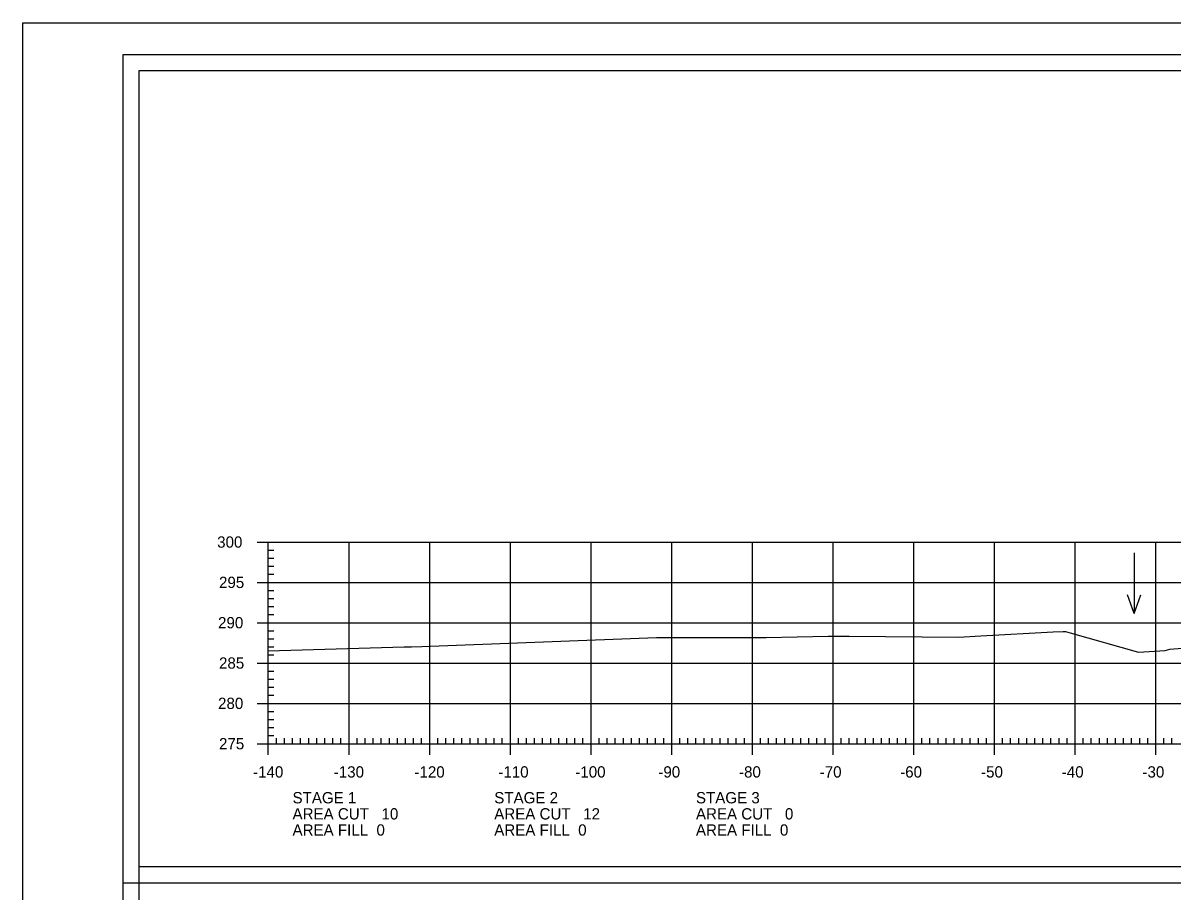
# Model space of a CAD drawing. Extents: x 1368713 to 1370673, y 380279 to 380950.
# Drawn here: x 1370339.2 to 1370481.6, y 380842.8 to 380950.4 of the extents above; entities that cross this region are included whole.
import ezdxf

# ---------------------------------------------------------------- set-up
doc = ezdxf.new("R2010")
doc.units = 0
for name, color, linetype in [('R_Axis', 7, 'Continuous'), ('R_Axis Annot', 7, 'Continuous'), ('R_Border', 7, 'Continuous'), ('R_Border Plan-Plan', 7, 'Continuous'), ('R_Exist Surface', 7, 'Continuous'), ('R_Grid', 7, 'Continuous'), ('R_No Plot', 7, 'Continuous'), ('R_Water Annot', 7, 'Continuous')]:
    doc.layers.add(name, color=color, linetype=linetype)

msp = doc.modelspace()

# ---------------------------------------------------------------- linework, layer by layer
at = {"layer": 'R_Axis'}
for p, q in [((1370368.23, 380886.09), (1370371.03, 380886.09)), ((1370369.63, 380861.09), (1370369.63, 380886.09)), ((1370369.63, 380885.09), (1370370.33, 380885.09)), ((1370369.63, 380884.09), (1370370.33, 380884.09)), ((1370369.63, 380883.09), (1370370.33, 380883.09)), ((1370369.63, 380882.09), (1370370.33, 380882.09)), ((1370368.23, 380881.09), (1370371.03, 380881.09)), ((1370369.63, 380880.09), (1370370.33, 380880.09)), ((1370369.63, 380879.09), (1370370.33, 380879.09)), ((1370369.63, 380878.09), (1370370.33, 380878.09)), ((1370369.63, 380877.09), (1370370.33, 380877.09)), ((1370368.23, 380876.09), (1370371.03, 380876.09)), ((1370369.63, 380875.09), (1370370.33, 380875.09)), ((1370369.63, 380874.09), (1370370.33, 380874.09)), ((1370369.63, 380873.09), (1370370.33, 380873.09)), ((1370368.23, 380871.09), (1370371.03, 380871.09)), ((1370369.63, 380872.09), (1370370.33, 380872.09)), ((1370369.63, 380870.09), (1370370.33, 380870.09)), ((1370369.63, 380869.09), (1370370.33, 380869.09)), ((1370369.63, 380868.09), (1370370.33, 380868.09)), ((1370369.63, 380867.09), (1370370.33, 380867.09)), ((1370368.23, 380866.09), (1370371.03, 380866.09)), ((1370369.63, 380865.09), (1370370.33, 380865.09)), ((1370369.63, 380864.09), (1370370.33, 380864.09)), ((1370369.63, 380863.09), (1370370.33, 380863.09)), ((1370369.63, 380859.69), (1370369.63, 380862.49)), ((1370379.63, 380859.69), (1370379.63, 380862.49)), ((1370389.63, 380859.69), (1370389.63, 380862.49)), ((1370399.63, 380859.69), (1370399.63, 380862.49)), ((1370409.63, 380859.69), (1370409.63, 380862.49)), ((1370419.63, 380859.69), (1370419.63, 380862.49)), ((1370429.63, 380859.69), (1370429.63, 380862.49)), ((1370439.63, 380859.69), (1370439.63, 380862.49)), ((1370449.63, 380859.69), (1370449.63, 380862.49)), ((1370459.63, 380859.69), (1370459.63, 380862.49)), ((1370469.63, 380859.69), (1370469.63, 380862.49)), ((1370479.63, 380859.69), (1370479.63, 380862.49)), ((1370368.23, 380861.09), (1370371.03, 380861.09)), ((1370369.63, 380862.09), (1370370.33, 380862.09)), ((1370369.63, 380861.09), (1370649.63, 380861.09)), ((1370370.63, 380861.09), (1370370.63, 380861.79)), ((1370371.63, 380861.09), (1370371.63, 380861.79)), ((1370372.63, 380861.09), (1370372.63, 380861.79)), ((1370373.63, 380861.09), (1370373.63, 380861.79)), ((1370374.63, 380861.09), (1370374.63, 380861.79)), ((1370375.63, 380861.09), (1370375.63, 380861.79)), ((1370376.63, 380861.09), (1370376.63, 380861.79)), ((1370377.63, 380861.09), (1370377.63, 380861.79)), ((1370378.63, 380861.09), (1370378.63, 380861.79)), ((1370380.63, 380861.09), (1370380.63, 380861.79)), ((1370381.63, 380861.09), (1370381.63, 380861.79)), ((1370382.63, 380861.09), (1370382.63, 380861.79)), ((1370383.63, 380861.09), (1370383.63, 380861.79)), ((1370384.63, 380861.09), (1370384.63, 380861.79)), ((1370385.63, 380861.09), (1370385.63, 380861.79)), ((1370386.63, 380861.09), (1370386.63, 380861.79)), ((1370387.63, 380861.09), (1370387.63, 380861.79)), ((1370388.63, 380861.09), (1370388.63, 380861.79)), ((1370390.63, 380861.09), (1370390.63, 380861.79)), ((1370391.63, 380861.09), (1370391.63, 380861.79)), ((1370392.63, 380861.09), (1370392.63, 380861.79)), ((1370393.63, 380861.09), (1370393.63, 380861.79)), ((1370394.63, 380861.09), (1370394.63, 380861.79)), ((1370395.63, 380861.09), (1370395.63, 380861.79)), ((1370396.63, 380861.09), (1370396.63, 380861.79)), ((1370397.63, 380861.09), (1370397.63, 380861.79)), ((1370398.63, 380861.09), (1370398.63, 380861.79)), ((1370400.63, 380861.09), (1370400.63, 380861.79)), ((1370401.63, 380861.09), (1370401.63, 380861.79)), ((1370402.63, 380861.09), (1370402.63, 380861.79)), ((1370403.63, 380861.09), (1370403.63, 380861.79)), ((1370404.63, 380861.09), (1370404.63, 380861.79)), ((1370405.63, 380861.09), (1370405.63, 380861.79)), ((1370406.63, 380861.09), (1370406.63, 380861.79)), ((1370407.63, 380861.09), (1370407.63, 380861.79)), ((1370408.63, 380861.09), (1370408.63, 380861.79)), ((1370410.63, 380861.09), (1370410.63, 380861.79)), ((1370411.63, 380861.09), (1370411.63, 380861.79)), ((1370412.63, 380861.09), (1370412.63, 380861.79)), ((1370413.63, 380861.09), (1370413.63, 380861.79)), ((1370414.63, 380861.09), (1370414.63, 380861.79)), ((1370415.63, 380861.09), (1370415.63, 380861.79)), ((1370416.63, 380861.09), (1370416.63, 380861.79)), ((1370417.63, 380861.09), (1370417.63, 380861.79)), ((1370418.63, 380861.09), (1370418.63, 380861.79)), ((1370420.63, 380861.09), (1370420.63, 380861.79)), ((1370421.63, 380861.09), (1370421.63, 380861.79)), ((1370422.63, 380861.09), (1370422.63, 380861.79)), ((1370423.63, 380861.09), (1370423.63, 380861.79)), ((1370424.63, 380861.09), (1370424.63, 380861.79)), ((1370425.63, 380861.09), (1370425.63, 380861.79)), ((1370426.63, 380861.09), (1370426.63, 380861.79)), ((1370427.63, 380861.09), (1370427.63, 380861.79)), ((1370428.63, 380861.09), (1370428.63, 380861.79)), ((1370430.63, 380861.09), (1370430.63, 380861.79)), ((1370431.63, 380861.09), (1370431.63, 380861.79)), ((1370432.63, 380861.09), (1370432.63, 380861.79)), ((1370433.63, 380861.09), (1370433.63, 380861.79)), ((1370434.63, 380861.09), (1370434.63, 380861.79)), ((1370435.63, 380861.09), (1370435.63, 380861.79)), ((1370436.63, 380861.09), (1370436.63, 380861.79)), ((1370437.63, 380861.09), (1370437.63, 380861.79)), ((1370438.63, 380861.09), (1370438.63, 380861.79)), ((1370440.63, 380861.09), (1370440.63, 380861.79)), ((1370441.63, 380861.09), (1370441.63, 380861.79)), ((1370442.63, 380861.09), (1370442.63, 380861.79)), ((1370443.63, 380861.09), (1370443.63, 380861.79)), ((1370444.63, 380861.09), (1370444.63, 380861.79)), ((1370445.63, 380861.09), (1370445.63, 380861.79)), ((1370446.63, 380861.09), (1370446.63, 380861.79)), ((1370447.63, 380861.09), (1370447.63, 380861.79)), ((1370448.63, 380861.09), (1370448.63, 380861.79)), ((1370450.63, 380861.09), (1370450.63, 380861.79)), ((1370451.63, 380861.09), (1370451.63, 380861.79)), ((1370452.63, 380861.09), (1370452.63, 380861.79)), ((1370453.63, 380861.09), (1370453.63, 380861.79)), ((1370454.63, 380861.09), (1370454.63, 380861.79)), ((1370455.63, 380861.09), (1370455.63, 380861.79)), ((1370456.63, 380861.09), (1370456.63, 380861.79)), ((1370457.63, 380861.09), (1370457.63, 380861.79)), ((1370458.63, 380861.09), (1370458.63, 380861.79)), ((1370460.63, 380861.09), (1370460.63, 380861.79)), ((1370461.63, 380861.09), (1370461.63, 380861.79)), ((1370462.63, 380861.09), (1370462.63, 380861.79)), ((1370463.63, 380861.09), (1370463.63, 380861.79)), ((1370464.63, 380861.09), (1370464.63, 380861.79)), ((1370465.63, 380861.09), (1370465.63, 380861.79)), ((1370466.63, 380861.09), (1370466.63, 380861.79)), ((1370467.63, 380861.09), (1370467.63, 380861.79)), ((1370468.63, 380861.09), (1370468.63, 380861.79)), ((1370470.63, 380861.09), (1370470.63, 380861.79)), ((1370471.63, 380861.09), (1370471.63, 380861.79)), ((1370472.63, 380861.09), (1370472.63, 380861.79)), ((1370473.63, 380861.09), (1370473.63, 380861.79)), ((1370474.63, 380861.09), (1370474.63, 380861.79)), ((1370475.63, 380861.09), (1370475.63, 380861.79)), ((1370476.63, 380861.09), (1370476.63, 380861.79)), ((1370477.63, 380861.09), (1370477.63, 380861.79)), ((1370478.63, 380861.09), (1370478.63, 380861.79)), ((1370480.63, 380861.09), (1370480.63, 380861.79)), ((1370481.63, 380861.09), (1370481.63, 380861.79))]:
    msp.add_line(p, q, dxfattribs=at)
at = {"layer": 'R_Border'}
for p, q in [((1370351.63, 380946.55), (1370667.81, 380946.55)), ((1370351.63, 380741.09), (1370351.63, 380946.55))]:
    msp.add_line(p, q, dxfattribs=at)
at = {"layer": 'R_Border Plan-Plan'}
msp.add_line((1370351.63, 380843.82), (1370667.81, 380843.82), dxfattribs=at)
at = {"layer": 'R_Exist Surface'}
msp.add_lwpolyline([(1370369.63, 380872.6), (1370386.45, 380873.08), (1370387.01, 380873.1), (1370387.38, 380873.11), (1370388.64, 380873.15), (1370417.72, 380874.24), (1370427.03, 380874.24), (1370431.33, 380874.26), (1370439, 380874.41), (1370441.61, 380874.43), (1370455.18, 380874.29), (1370457.95, 380874.48), (1370466.89, 380874.94), (1370468.13, 380875.01), (1370468.43, 380874.99), (1370469.03, 380874.82), (1370477.48, 380872.44), (1370480.79, 380872.65), (1370481.37, 380872.82), (1370490.12, 380873.52)], dxfattribs=at)
at = {"layer": 'R_Grid'}
for p, q in [((1370369.63, 380886.09), (1370649.63, 380886.09)), ((1370369.63, 380861.09), (1370369.63, 380886.09)), ((1370379.63, 380861.09), (1370379.63, 380886.09)), ((1370389.63, 380861.09), (1370389.63, 380886.09)), ((1370399.63, 380861.09), (1370399.63, 380886.09)), ((1370409.63, 380861.09), (1370409.63, 380886.09)), ((1370419.63, 380861.09), (1370419.63, 380886.09)), ((1370429.63, 380861.09), (1370429.63, 380886.09)), ((1370439.63, 380861.09), (1370439.63, 380886.09)), ((1370449.63, 380861.09), (1370449.63, 380886.09)), ((1370459.63, 380861.09), (1370459.63, 380886.09)), ((1370469.63, 380861.09), (1370469.63, 380886.09)), ((1370479.63, 380861.09), (1370479.63, 380886.09)), ((1370369.63, 380881.09), (1370649.63, 380881.09)), ((1370369.63, 380876.09), (1370649.63, 380876.09)), ((1370369.63, 380871.09), (1370649.63, 380871.09)), ((1370369.63, 380866.09), (1370649.63, 380866.09)), ((1370369.63, 380861.09), (1370649.63, 380861.09))]:
    msp.add_line(p, q, dxfattribs=at)
at = {"layer": 'R_No Plot'}
for points in [[(1370339.22, 380950.45), (1370672.56, 380950.45), (1370672.56, 380737.11), (1370339.22, 380737.11)], [(1370665.81, 380845.82), (1370353.63, 380845.82), (1370353.63, 380944.55), (1370603.17, 380944.55), (1370603.17, 380934.67), (1370620.71, 380934.67), (1370644.81, 380934.67), (1370644.81, 380912.34), (1370665.81, 380912.34)], [(1370353.63, 380944.55), (1370603.17, 380944.55), (1370603.17, 380934.67), (1370620.71, 380934.67), (1370644.81, 380934.67), (1370644.81, 380912.34), (1370665.81, 380912.34), (1370665.81, 380743.09), (1370353.63, 380743.09)]]:
    msp.add_lwpolyline(points, close=True, dxfattribs=at)
at = {"layer": 'R_Water Annot'}
for p, q in [((1370476.94, 380884.76), (1370476.94, 380877.22)), ((1370476.94, 380877.22), (1370476.1, 380879.53)), ((1370476.94, 380877.22), (1370477.78, 380879.53))]:
    msp.add_line(p, q, dxfattribs=at)

# ---------------------------------------------------------------- texts
at = {"layer": 'R_Axis Annot'}
for s, p in [('300', (1370363.29, 380885.39)), ('295', (1370363.52, 380880.39)), ('290', (1370363.4, 380875.39)), ('285', (1370363.52, 380870.39)), ('280', (1370363.4, 380865.39)), ('275', (1370363.52, 380860.39)), ('-140', (1370367.74, 380856.89)), ('-130', (1370377.74, 380856.89)), ('-120', (1370387.74, 380856.89)), ('-110', (1370398.14, 380856.89)), ('-100', (1370407.68, 380856.89)), ('-90', (1370417.97, 380856.89)), ('-80', (1370427.97, 380856.89)), ('-70', (1370437.97, 380856.89)), ('-60', (1370447.94, 380856.89)), ('-50', (1370457.97, 380856.89)), ('-40', (1370467.97, 380856.89)), ('-30', (1370477.97, 380856.89)), ('STAGE 1', (1370372.63, 380853.69)), ('STAGE 2', (1370397.63, 380853.69)), ('STAGE 3', (1370422.63, 380853.69)), ('AREA CUT   10', (1370372.63, 380851.69)), ('AREA CUT   12', (1370397.63, 380851.69)), ('AREA CUT   0', (1370422.63, 380851.69)), ('AREA FILL  0', (1370372.63, 380849.69)), ('AREA FILL  0', (1370397.63, 380849.69)), ('AREA FILL  0', (1370422.63, 380849.69))]:
    msp.add_text(s, height=1.4, dxfattribs=at).set_placement(p)

doc.saveas('drawing.dxf')
